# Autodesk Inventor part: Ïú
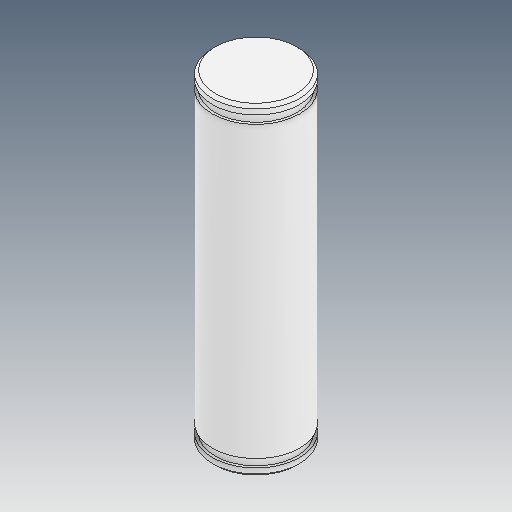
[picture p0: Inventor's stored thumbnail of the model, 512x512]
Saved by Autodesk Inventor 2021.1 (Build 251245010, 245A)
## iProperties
Created: 2021-05
Part Number: Ïú
Material: Ogólny
Document SubType Name: Modeling
Designer: user
Density: 1 g/cm^3
Appearance: Domyślna
Author: user
Revision Number: ÈÎºÎ
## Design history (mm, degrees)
feature "ÊäÈë1"
node "Bryła1"
